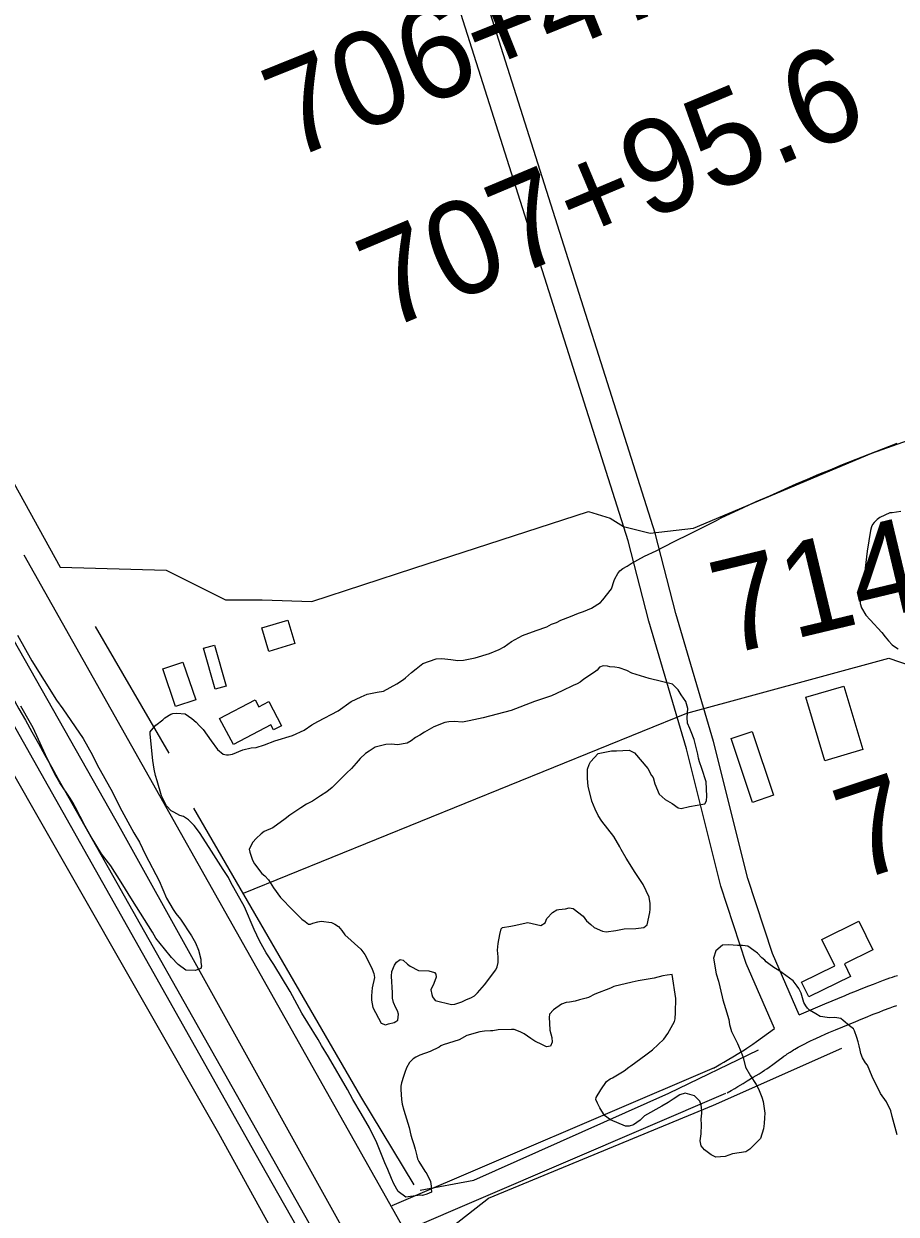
# Model space of a CAD drawing. Extents: x 3161564 to 3199464, y 849354 to 874788.
# Drawn here: x 3173790 to 3174720, y 858211 to 859480 of the extents above; entities that cross this region are included whole.
import ezdxf

# ---------------------------------------------------------------- set-up
doc = ezdxf.new("R2010")
doc.units = 0
for name, color, linetype in [('V-BLDG-OTLN', 7, 'Continuous'), ('V-RAIL-TRAK', 7, 'Continuous'), ('V-ROAD-CNTR', 7, 'Continuous'), ('V-SITE-VEGE', 7, 'Continuous'), ('V-SURV-IDEN', 7, 'Continuous'), ('V-TOPO-SHOR', 7, 'Continuous')]:
    doc.layers.add(name, color=color, linetype=linetype)

msp = doc.modelspace()

# ---------------------------------------------------------------- linework, layer by layer
at = {"layer": 'V-BLDG-OTLN'}
for points in [[(3174051.8, 858811), (3174044.3, 858836.2), (3174071.9, 858844.4), (3174079.4, 858819.3)], [(3173993.8, 858817.8), (3174006.2, 858774.1), (3173994.3, 858770.7), (3173981.9, 858814.4)], [(3173960.1, 858799.6), (3173973.7, 858759.5), (3173952.1, 858752.2), (3173938.5, 858792.3)], [(3174664.4, 858774.1), (3174684.6, 858706.4), (3174644.3, 858694.4), (3174624.1, 858762.1)], [(3173999.2, 858739.5), (3174036.9, 858759.4), (3174040.8, 858752), (3174051.5, 858757.6), (3174065.1, 858731.8), (3174056.5, 858727.3), (3174053.6, 858732.8), (3174013.8, 858711.8)], [(3174544.4, 858718.1), (3174566.9, 858725.6), (3174589.6, 858657.7), (3174567.1, 858650.2)], [(3174627.1, 858442.8), (3174619.3, 858458.5), (3174654.8, 858476), (3174641, 858504), (3174680.3, 858523.5), (3174695.4, 858492.9), (3174665.1, 858478), (3174671.7, 858464.7)]]:
    msp.add_lwpolyline(points, close=True, dxfattribs=at)
at = {"layer": 'V-RAIL-TRAK'}
msp.add_lwpolyline([(3174157.4, 858064.1), (3174037.2, 858276.4), (3173924.9, 858475.8), (3173766.8, 858756), (3173598.6, 859058.1), (3173559.2, 859126.8), (3173511.6, 859217.6), (3173461.3, 859309.7), (3173401.1, 859429.8), (3173339.3, 859554.9), (3173282.5, 859673), (3173217.6, 859812.9), (3173178.8, 859898.6), (3173125.5, 860017), (3173048.9, 860197.7), (3172969.1, 860400.4)], dxfattribs=at)
at = {"layer": 'V-ROAD-CNTR'}
for points in [[(3174590.5, 858409.3), (3174560.5, 858478.6), (3174533.5, 858560.8), (3174496.7, 858707.2), (3174456.5, 858843.4), (3174434.7, 858928.7), (3174172, 859756.3), (3174151, 859792.8), (3174138.4, 859819.1), (3174085.6, 859859.3), (3174067.2, 859912.2), (3174080.5, 859976.7), (3174074.4, 860003.8), (3173838.8, 860693.3)], [(3174616.9, 858423.8), (3174588.6, 858489.2), (3174562.3, 858569.2), (3174525.6, 858715.1), (3174485.4, 858851.3), (3174463.5, 858937), (3174199.7, 859768.5), (3174177.6, 859806.8), (3174172, 859818.4)], [(3173790.5, 858913.8), (3174494.5, 857665.3), (3175266.5, 856298.7), (3175883.3, 855209.3)], [(3173833.8, 858663.3), (3175153.4, 856327.2)], [(3174616.9, 858423.8), (3174636.7, 858432.4), (3174644.1, 858435.5), (3174665.9, 858444.5), (3174671.4, 858446.8), (3174676.3, 858448.8), (3174684.7, 858452.2), (3174691.1, 858454.7), (3174696, 858456.6), (3174703.2, 858459.4), (3174706.9, 858460.7), (3174710.6, 858462.1), (3174713.5, 858463.1), (3174716.3, 858464.1), (3174719, 858465), (3174721.7, 858465.8)], [(3174540, 858340.8), (3174544.4, 858343.3), (3174548.2, 858345.4), (3174551.5, 858347.4), (3174557.3, 858350.7), (3174561.6, 858353.3), (3174568, 858357.2), (3174574.4, 858361.1), (3174577.3, 858362.9), (3174580, 858364.7), (3174582.5, 858366.4), (3174584.8, 858368), (3174588.9, 858371), (3174595.9, 858376.1), (3174598.5, 858378), (3174600.7, 858379.6), (3174602.6, 858380.9), (3174604.2, 858382.1), (3174607.2, 858384.1), (3174609.3, 858385.5), (3174610.9, 858386.5), (3174612.1, 858387.2), (3174613.9, 858388.2), (3174615.8, 858389.3), (3174619.4, 858391.2), (3174622.8, 858392.9), (3174626.1, 858394.6), (3174629.1, 858396), (3174632, 858397.4), (3174634.8, 858398.7), (3174640, 858401), (3174644.5, 858403.1), (3174648.5, 858404.8), (3174655.7, 858407.8), (3174677.4, 858416.8), (3174682.9, 858419.1), (3174687.6, 858421), (3174695.8, 858424.4), (3174702, 858426.8), (3174706.7, 858428.6), (3174713.7, 858431.3), (3174717.3, 858432.6), (3174720.8, 858433.8)], [(3174525.5, 858367.1), (3174529.7, 858369.4), (3174533.3, 858371.5), (3174536.5, 858373.3), (3174542, 858376.6), (3174546.2, 858379), (3174552.4, 858382.8), (3174558.6, 858386.6), (3174561.1, 858388.2), (3174563.3, 858389.6), (3174565.5, 858391.1), (3174567.5, 858392.5), (3174571.3, 858395.3), (3174590.5, 858409.3)], [(3174183.2, 858220.6), (3174526.8, 858367.8)], [(3174195, 858193), (3174538.6, 858340.2)]]:
    msp.add_lwpolyline(points, dxfattribs=at)
msp.add_spline([(3172633.8, 861383.8), (3172802.6, 860880.5), (3172972.2, 860440.5), (3173132.3, 860039.3), (3173355.9, 859565.2), (3173614.6, 859060.8), (3173833.8, 858663.3)], degree=3, dxfattribs=at)
at = {"layer": 'V-SITE-VEGE'}
for points in [[(3174433.4, 858901.7), (3174437.9, 858904.6), (3174452.1, 858912.5), (3174464.4, 858918.2), (3174482.8, 858927.9), (3174501.1, 858936.5), (3174528.8, 858950.5), (3174533.6, 858953.4), (3174557.5, 858964.5), (3174571, 858970.6), (3174585.6, 858976.7), (3174613.6, 858989.5), (3174625.6, 858994.5), (3174637.9, 858999.9), (3174649.8, 859004.5), (3174662.9, 859010.2), (3174721.5, 859033)], [(3174725.4, 858960), (3174716.1, 858958.6), (3174713.6, 858958.7), (3174702.7, 858953.7), (3174700.1, 858951.5), (3174696.7, 858948.2), (3174695.2, 858946.4), (3174694, 858943.8), (3174692.8, 858939.7), (3174689.5, 858917.9), (3174685.7, 858887.5), (3174681.6, 858866.8), (3174681.9, 858862), (3174683.3, 858857.5), (3174688, 858849.7), (3174692.4, 858844.8), (3174705.1, 858831.2), (3174708.4, 858826.7), (3174712, 858822.2), (3174716, 858818.1), (3174718.6, 858816.2), (3174722.3, 858813.9)], [(3174141.3, 858333.5), (3174135.5, 858344.3), (3174115.3, 858379.2), (3174107.8, 858391.2), (3174104.2, 858397.5), (3174093.3, 858415.1), (3174086.8, 858425.6), (3174074.2, 858448.5), (3174056.9, 858477.3), (3174048.9, 858490), (3174041.7, 858502.8), (3174036, 858514.7), (3174025.6, 858538.7), (3174011.2, 858564.9), (3174008.7, 858570.1), (3174002.9, 858578.7), (3173988.1, 858602), (3173977.6, 858618.1), (3173972.2, 858625.6), (3173966, 858631.6), (3173960.5, 858635.1), (3173956.8, 858636.2), (3173950.2, 858639.7), (3173947.6, 858641.2), (3173942.5, 858646.5), (3173940.3, 858650.6), (3173937.1, 858657.3), (3173932.5, 858673), (3173930.8, 858678.9), (3173929.4, 858685.6), (3173928.1, 858694.9), (3173925.2, 858722.8), (3173925.3, 858725.4), (3173926.4, 858727.2), (3173931.3, 858732.4), (3173938.5, 858738.2), (3173940.7, 858740.4), (3173947.1, 858744.3), (3173949.3, 858745), (3173953.4, 858745.3), (3173962.3, 858744.4), (3173969.6, 858739.5), (3173974, 858735.7), (3173977.7, 858731.6), (3173981.7, 858727.8), (3173990, 858715.8), (3173996.9, 858706.4), (3174002.8, 858701.5), (3174006.4, 858700.7), (3174008.7, 858700.7), (3174012.8, 858701.7), (3174024, 858706.3), (3174032.9, 858708.4), (3174038.1, 858708.7), (3174047.1, 858711.5), (3174057.9, 858715.8), (3174076.9, 858721.4), (3174089.2, 858727.1), (3174097.5, 858732.9), (3174103.9, 858736.5), (3174125.5, 858747.7), (3174139.4, 858757.5), (3174149.9, 858762.5), (3174156.6, 858765.3), (3174167.1, 858767.7), (3174173.7, 858768.7), (3174188, 858776.3), (3174195.1, 858781), (3174197.3, 858782.8), (3174203.7, 858788.6), (3174208.6, 858792.6), (3174215.8, 858798.1), (3174230, 858803.1), (3174235.9, 858803.3), (3174245.5, 858802.4), (3174252.9, 858801.2), (3174259.2, 858801.8), (3174271.5, 858804.2), (3174286.8, 858808.8), (3174297.3, 858813.1), (3174302.5, 858815.9), (3174310.4, 858821.4), (3174322, 858827.9), (3174336.5, 858833.2), (3174348.1, 858837.1), (3174353, 858840), (3174358.2, 858841.7), (3174363, 858844.2), (3174373.1, 858848.1), (3174381.7, 858851.7), (3174386.9, 858853.5), (3174395.5, 858857), (3174405.3, 858863.2), (3174407.5, 858865.8), (3174417, 858877.8), (3174419.8, 858886.7), (3174420.5, 858888.5), (3174423.6, 858894), (3174425.9, 858897), (3174428.9, 858899.5), (3174433.4, 858901.7)], [(3173783.8, 858828.2), (3173798.9, 858800.9), (3173825.3, 858759.2), (3173832.2, 858749.9), (3173853.9, 858718.3), (3173863.7, 858700.4), (3173868.7, 858690.3), (3173884.9, 858661.1), (3173892.8, 858645), (3173907.9, 858617.7), (3173913.7, 858607.6)], [(3174457.6, 858532.7), (3174458, 858536.4), (3174458.1, 858542.3), (3174457.1, 858549), (3174450.7, 858562.5), (3174442, 858575.6), (3174432.6, 858590.6), (3174427.2, 858599.9), (3174425.7, 858602.9), (3174419.3, 858613.8), (3174406.5, 858630), (3174402.6, 858636.3), (3174399.3, 858643.1), (3174395.8, 858651.6), (3174392, 858667.3), (3174391.3, 858675.5), (3174391.1, 858685.5), (3174393.1, 858690.6), (3174394.6, 858693.2), (3174402.6, 858702.3), (3174416.7, 858705.1), (3174422.3, 858705), (3174435.6, 858705.9), (3174441.5, 858702.8), (3174455.7, 858686.3), (3174459.6, 858678.8), (3174461.1, 858676.5), (3174463.2, 858669.8), (3174467.5, 858659), (3174474.1, 858653.3), (3174481.4, 858649.1), (3174488, 858644.5), (3174491, 858643.8), (3174499.9, 858645.8), (3174516.3, 858648.5), (3174518.2, 858651.8), (3174518.6, 858656.7), (3174517.8, 858671.9), (3174513.2, 858686.4), (3174510.7, 858693.5), (3174509.7, 858697.2), (3174509, 858701.7), (3174504.8, 858717), (3174501.6, 858725.2), (3174500.5, 858728.9), (3174498, 858734.5), (3174497.4, 858740.5), (3174498.3, 858750.1), (3174496.2, 858757.5), (3174491.1, 858764.7), (3174487.9, 858769.9), (3174481.7, 858776), (3174456.9, 858782.3), (3174438.5, 858787.8), (3174433.3, 858790.5), (3174425.2, 858793.6), (3174420.4, 858794.4), (3174415.2, 858794.5), (3174412.6, 858795.3), (3174407.8, 858795.7), (3174404.1, 858794.3), (3174401.4, 858791), (3174398.8, 858788.8), (3174387.5, 858781.6), (3174383.4, 858778.3), (3174380.4, 858776.5), (3174375.9, 858774.7), (3174364.3, 858769), (3174352.8, 858763.6), (3174334.9, 858757.6), (3174309.8, 858748), (3174280, 858740.4), (3174265.1, 858736.9), (3174258.1, 858735.5), (3174249.2, 858736.4), (3174243.6, 858736.1), (3174239.2, 858735.1), (3174227.6, 858730.5), (3174217.5, 858725.1), (3174212.6, 858721.8), (3174208.1, 858719.3), (3174203.2, 858715.7), (3174199.1, 858713.1), (3174188.7, 858711.5), (3174182.4, 858712.3), (3174176.5, 858711.7), (3174164.9, 858708.9), (3174158.5, 858704.9), (3174154.8, 858702.4), (3174148.8, 858696.9), (3174144.6, 858691.8), (3174139.7, 858686.3), (3174134.4, 858681.2), (3174119.3, 858665.9), (3174113.3, 858661.5), (3174106.6, 858657.2), (3174098.3, 858651.4), (3174091.9, 858648.2), (3174085.9, 858644.2), (3174073.9, 858636.6), (3174069.1, 858632.6)], [(3173913.7, 858607.6), (3173920.1, 858594.1), (3173934.9, 858566.4), (3173942.7, 858548.1), (3173949.6, 858536.1), (3173952.5, 858531.6), (3173957.6, 858525.6), (3173969.1, 858508), (3173973.5, 858500.5), (3173976.7, 858492.6), (3173979.1, 858483), (3173979.1, 858479.6), (3173979.7, 858475.5), (3173979, 858473.3), (3173976.3, 858472.2), (3173973, 858471.2), (3173963.3, 858471.4), (3173954.9, 858477.4), (3173948, 858485), (3173940.3, 858494), (3173931.3, 858505.6), (3173927.7, 858512), (3173906.3, 858545.7), (3173894.4, 858565.2), (3173883.2, 858582.5), (3173873.4, 858595.2), (3173862.2, 858613.6), (3173855.7, 858624.8), (3173845.3, 858645.4), (3173842.8, 858649.9), (3173839.9, 858654.8), (3173829, 858670.9), (3173823.6, 858680.3), (3173813.6, 858700.8), (3173800.4, 858729.6), (3173797.5, 858734.5), (3173787.4, 858752.5)], [(3174069.1, 858632.6), (3174055.9, 858623.2), (3174046.6, 858619.2), (3174043.6, 858616.7), (3174038.3, 858611.6), (3174034.5, 858607.6), (3174030.7, 858600.2), (3174031.4, 858597.2), (3174034.2, 858588.7)], [(3174034.2, 858588.7), (3174036.4, 858584.6), (3174044, 858574.4), (3174047.3, 858571.8), (3174051.3, 858567.6), (3174056.7, 858559), (3174064, 858548.9), (3174077.1, 858535.3), (3174086.9, 858525.8), (3174090.2, 858523.2), (3174093.9, 858520.5), (3174096.1, 858520.5), (3174098.7, 858521.6), (3174104, 858523), (3174107.3, 858523.7), (3174118.4, 858522), (3174122.1, 858520.4), (3174125.8, 858517.8), (3174129.4, 858513.6), (3174132.7, 858509.1), (3174149.8, 858493.6), (3174153.8, 858488), (3174159.2, 858477.9), (3174161.7, 858472.3), (3174163.5, 858467.8), (3174164.2, 858463.7), (3174161.8, 858452.6), (3174160.9, 858444.1), (3174161.2, 858439.3), (3174162.5, 858431.5), (3174171.2, 858415), (3174175.9, 858413.1), (3174179.3, 858414.2), (3174185.3, 858415.5), (3174187.1, 858416.6), (3174189, 858418.1), (3174189.9, 858424.4), (3174188.8, 858428.1), (3174187, 858431.1), (3174184.5, 858437.1), (3174183.5, 858441.5), (3174183.6, 858447.1), (3174182.4, 858464.9), (3174182.8, 858470.1), (3174185.5, 858476.7), (3174187.8, 858480), (3174191.6, 858482.6), (3174194.9, 858482.1), (3174199.6, 858477.6), (3174202.2, 858475.7), (3174211, 858471.1), (3174222.1, 858470.6), (3174228.1, 858469), (3174229.5, 858467.1), (3174229.8, 858464.1), (3174227.5, 858457.1), (3174224.4, 858450.5), (3174225.4, 858445.3), (3174226.1, 858443), (3174229, 858438.9), (3174246.4, 858434.9), (3174249.7, 858435.2), (3174257.2, 858437.7), (3174262.4, 858440.2), (3174266.9, 858442), (3174270.7, 858444.2), (3174274.1, 858447.4), (3174281.6, 858455.8), (3174293.4, 858471.6), (3174294.9, 858474.9), (3174296.1, 858479.7), (3174296.2, 858485.7), (3174295.2, 858492.7), (3174296.1, 858499.7), (3174297.7, 858509.4), (3174299.3, 858515.3), (3174300.8, 858516.7), (3174309.4, 858518.1), (3174313.1, 858519.1), (3174327.6, 858522.2), (3174341.6, 858519), (3174346.1, 858521.9), (3174348.1, 858526.3), (3174354.1, 858532.9), (3174358.6, 858535.8), (3174360.8, 858536.1), (3174367.9, 858536.8), (3174371.6, 858537.8), (3174376.1, 858537), (3174386.7, 858529), (3174390.3, 858524.1), (3174394.7, 858520), (3174398.4, 858517), (3174407.2, 858513.1), (3174411.3, 858512.3), (3174421.3, 858513.6), (3174430.2, 858515.3), (3174442.8, 858515.9), (3174451.4, 858516.8), (3174454.8, 858519.7), (3174457.6, 858532.7)], [(3174715.9, 858315.4), (3174714.5, 858321.4), (3174709.8, 858331.1), (3174703.7, 858340.1), (3174694.7, 858358), (3174689.7, 858370), (3174687.5, 858372.6), (3174684.3, 858377.9), (3174682.5, 858382.7), (3174681.8, 858386.1), (3174680.8, 858390.9), (3174679.8, 858395), (3174678.4, 858399.8), (3174675.9, 858406.6), (3174674.8, 858408.8), (3174670.4, 858412.2), (3174663.8, 858417.9), (3174661.3, 858419.8), (3174655, 858421), (3174648.7, 858420.7), (3174642, 858421.6), (3174639.4, 858422), (3174634.6, 858425), (3174628, 858428.9), (3174625.8, 858430.8), (3174624, 858433.4), (3174621.9, 858437.1), (3174619, 858446.8), (3174616.5, 858451.7), (3174614.7, 858454.3), (3174610.4, 858459.9), (3174598.6, 858468.7), (3174595.3, 858471), (3174589.8, 858474.4), (3174584.7, 858478.2), (3174581.8, 858480.1), (3174580.3, 858482), (3174577, 858484.6), (3174572.3, 858489.5), (3174568.6, 858492.5), (3174562, 858497.1), (3174556.5, 858497.6), (3174551.3, 858497.6), (3174542, 858498.5), (3174535.3, 858497.9), (3174528.2, 858492.1), (3174525.5, 858484), (3174528.5, 858467.6), (3174531, 858459.8), (3174534.8, 858443), (3174535.5, 858439.7), (3174538.3, 858430.7), (3174541.8, 858418.8), (3174542.5, 858413.6), (3174544.6, 858406.1), (3174551, 858393.1), (3174554.9, 858384.1), (3174557.1, 858378.5), (3174559.5, 858368.1), (3174564.9, 858358.7), (3174571.1, 858349.7), (3174573.6, 858344.8), (3174577.1, 858336.2), (3174578.6, 858331.4), (3174580.2, 858319.1), (3174580.1, 858313.9), (3174579.6, 858308), (3174578.8, 858302.5), (3174575.7, 858292.1), (3174564.4, 858280.8), (3174560.2, 858277.9), (3174545.7, 858275.6), (3174537.9, 858272.7), (3174528.2, 858272.2), (3174523.1, 858274.5), (3174515.8, 858279.8), (3174512.5, 858284.3), (3174511.5, 858289.5), (3174512.3, 858296.9), (3174512.9, 858306.9), (3174512.6, 858312.8), (3174513.1, 858319.1), (3174513.1, 858321.4), (3174512.5, 858328), (3174511.1, 858331.8), (3174505.2, 858337.4), (3174495.2, 858340.2), (3174489.7, 858338.4), (3174482.5, 858334.1), (3174477.3, 858330.5), (3174470.5, 858326.5), (3174452.2, 858316.1), (3174447.3, 858311.7), (3174440.2, 858306.6), (3174435.7, 858305.2), (3174431.6, 858305.3), (3174415.8, 858311.9), (3174409.5, 858316.4), (3174404.5, 858324.7), (3174402, 858329.5), (3174400.2, 858333.6)], [(3174400.2, 858333.6), (3174400.6, 858335.8), (3174405.5, 858343.9), (3174411.6, 858352.7), (3174415.4, 858355.6), (3174418, 858356.7), (3174430.4, 858364.3), (3174435.2, 858367.9), (3174437.5, 858369.4), (3174453.6, 858381), (3174460.4, 858386.4), (3174472.8, 858397.7), (3174477, 858403.9), (3174483.9, 858416.8), (3174484.7, 858419.4), (3174485.2, 858426.4), (3174485.4, 858441.2), (3174481.4, 858466.9), (3174476.2, 858465.9), (3174471.7, 858465.2), (3174462.4, 858462.8), (3174445.3, 858460.1), (3174439, 858458.7), (3174419.2, 858453.9), (3174415.9, 858452.1), (3174399.1, 858445.7), (3174392.3, 858442.4), (3174389.7, 858441.4), (3174382.7, 858439.6), (3174378.2, 858438.2), (3174372.2, 858437.2), (3174368.5, 858436.9), (3174363.7, 858435.1), (3174355, 858429), (3174350.9, 858424.6), (3174350.4, 858420.9), (3174350.7, 858414.9), (3174351.3, 858407.5), (3174353.4, 858399.7), (3174353.7, 858394.5), (3174351.8, 858390.4), (3174347.7, 858389.8), (3174343.3, 858391.7), (3174335.2, 858395.9), (3174330.8, 858398.6), (3174323.8, 858403.5), (3174319.4, 858405.8), (3174313.1, 858408.1), (3174310.2, 858408.2), (3174296.1, 858407.7), (3174290.5, 858406.7), (3174287.9, 858406.7), (3174281.6, 858406.4), (3174276.4, 858405.8), (3174262.6, 858401.6), (3174254.4, 858397.2), (3174237.6, 858392), (3174235, 858390.9), (3174233.1, 858389.4), (3174223.7, 858384.8), (3174212.6, 858380.9), (3174208.4, 858378.7), (3174205.4, 858376.9), (3174203.9, 858375.5), (3174201.7, 858372.9), (3174198.2, 858367.4), (3174196.7, 858362.2), (3174195.1, 858358.2), (3174193.1, 858351.5), (3174192.3, 858347.8), (3174192.3, 858344.1), (3174193.2, 858333.7), (3174193.9, 858328.5), (3174195.6, 858322.2), (3174201.3, 858303.9), (3174203, 858295.7), (3174204.4, 858290.9), (3174206.1, 858285.7), (3174207.5, 858280.8), (3174209.3, 858273.7), (3174210, 858270.4), (3174211.4, 858267.4), (3174217.9, 858257.3), (3174220.1, 858254.3), (3174224, 858246.1), (3174224.7, 858241.2), (3174224.6, 858238.6), (3174225, 858234.9), (3174220.1, 858232.8), (3174215.3, 858231.4), (3174213, 858231.8), (3174197.8, 858229.4), (3174189.4, 858235.5), (3174185, 858243.7), (3174182.5, 858249.3), (3174178.6, 858259), (3174175.4, 858266.1), (3174166.9, 858287.4), (3174159, 858303.5), (3174149.9, 858318.5), (3174141.3, 858333.5)], [(3174721.5, 858296), (3174715.9, 858315.4)]]:
    msp.add_lwpolyline(points, dxfattribs=at)
at = {"layer": 'V-TOPO-SHOR'}
msp.add_line((3173866.7, 858837.6), (3173944.9, 858702.6), dxfattribs=at)
for points in [[(3174130.4, 858196.3), (3173893.7, 858622.4), (3173743.7, 858886.2), (3173578.7, 859179.5), (3173435.8, 859452.8), (3173275.5, 859780.2), (3173169.5, 860013.3), (3173061, 860286.1), (3172920.5, 860639.1), (3172839.6, 860873.9), (3172752.4, 861106.2), (3172655.2, 861373.8)], [(3174273.5, 857798.4), (3173998.2, 858297.5), (3173671.3, 858869.5), (3173428, 859310.1), (3173342.7, 859494.8), (3173239.7, 859450.4)], [(3173942.3, 858897.5), (3174005.3, 858866), (3174044.4, 858866), (3174097.6, 858864.2), (3174206, 858899.7), (3174392.5, 858960.1), (3174415.6, 858953), (3174429.8, 858944.1), (3174458.2, 858937), (3174504.4, 858942.4), (3174694.5, 859022.3), (3175019.6, 859137.8), (3175051.6, 859155.5)], [(3173712.9, 859110.8), (3173829.2, 858900.7), (3173942.3, 858897.5)], [(3174024.8, 858553.3), (3174497.3, 858745.2), (3174712.3, 858803.8), (3174831.3, 858762.9), (3175161.7, 858864.2)], [(3173971.5, 858643.9), (3174149.2, 858336.6), (3174206, 858242.5)], [(3174213.1, 858237.1), (3174270, 858247.8), (3174477.8, 858340.2), (3174573.7, 858386.4)], [(3174239.8, 858192.7), (3174285.9, 858228.3), (3174525.7, 858327.7), (3174662.5, 858388.1)]]:
    msp.add_lwpolyline(points, dxfattribs=at)

# ---------------------------------------------------------------- texts
at = {"layer": 'V-SURV-IDEN'}
for s, rotation, p in [('706+47.9', 21.9236, (3174074.2, 859334)), ('707+95.6', 22.8007, (3174176.2, 859152.4)), ('714+56.9', 13.4614, (3174538.2, 858806.6)), ('716+36.6', 18.2782, (3174677.4, 858565.4))]:
    msp.add_text(s, height=100, rotation=rotation, dxfattribs=at).set_placement(p)

doc.saveas('drawing.dxf')
